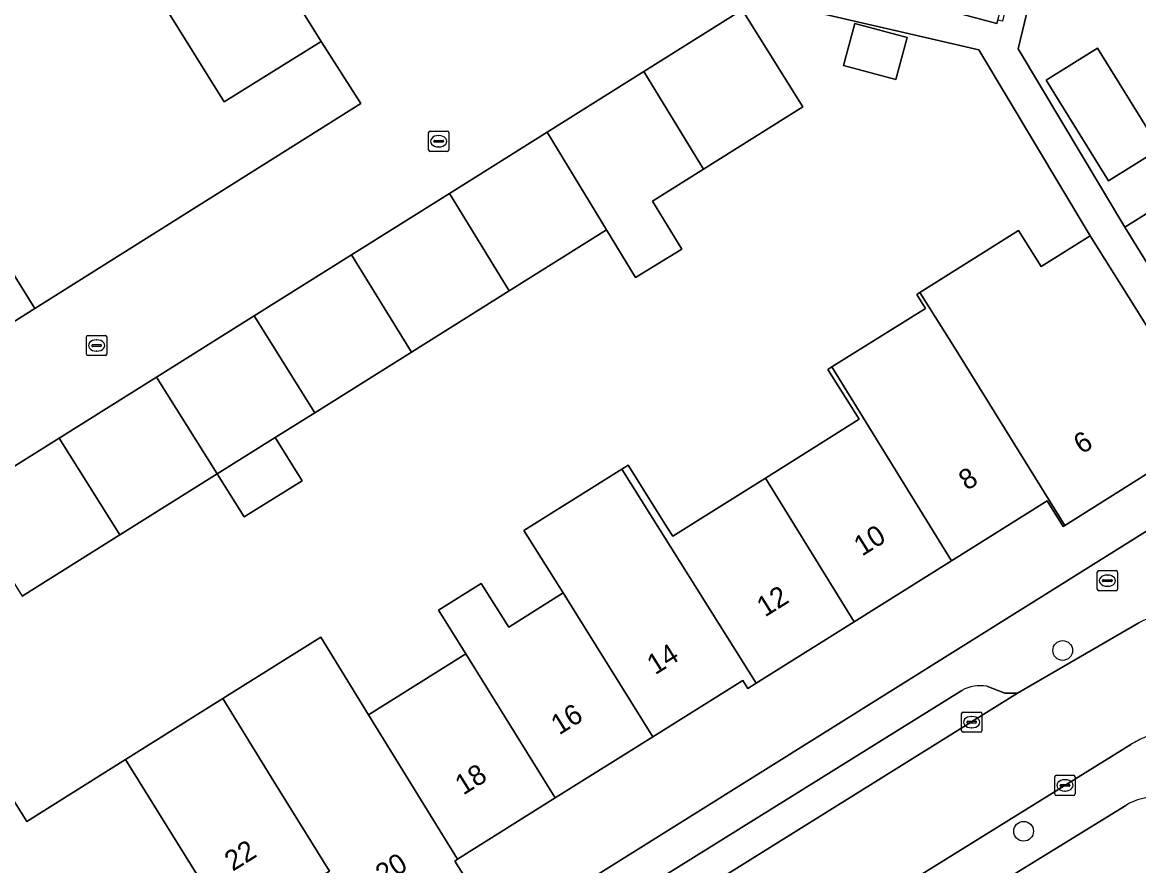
# Model space of a CAD drawing. Extents: x 157767 to 159172, y 387839 to 389425.
# Drawn here: x 158585.1 to 158640.4, y 388070.6 to 388112.4 of the extents above; entities that cross this region are included whole.
import ezdxf

# ---------------------------------------------------------------- set-up
doc = ezdxf.new("R2010")
doc.units = 0
for name, color, linetype in [('IMGEO_Boom', 7, 'Continuous'), ('IMGEO_Brandkraan', 7, 'Continuous'), ('IMGEO_Erf', 7, 'Continuous'), ('IMGEO_Kolk', 7, 'Continuous'), ('IMGEO_Muur', 7, 'Continuous'), ('IMGEO_Pand', 7, 'Continuous'), ('IMGEO_Pand_nummerreeks', 7, 'Continuous'), ('IMGEO_Parkeervlak_open', 7, 'Continuous'), ('IMGEO_Rijbaan_lokaal_open', 7, 'Continuous'), ('IMGEO_Rioolput', 7, 'Continuous'), ('IMGEO_Voetpad_open', 7, 'Continuous')]:
    doc.layers.add(name, color=color, linetype=linetype)

msp = doc.modelspace()

# ---------------------------------------------------------------- linework, layer by layer
at = {"layer": 'IMGEO_Boom'}
for centre in [(158636.608, 388081.306), (158634.673, 388072.349)]:
    msp.add_circle(centre, 0.489, dxfattribs=at)
at = {"layer": 'IMGEO_Brandkraan'}
for p, q in [((158638.322, 388084.338), (158638.322, 388085.19)), ((158638.397, 388085.264), (158639.249, 388085.264)), ((158639.323, 388085.19), (158639.323, 388084.338)), ((158638.581, 388084.758), (158638.581, 388084.77)), ((158639.019, 388084.721), (158638.621, 388084.721)), ((158638.624, 388084.807), (158639.022, 388084.807)), ((158638.81, 388085.044), (158638.835, 388085.044)), ((158639.065, 388084.77), (158639.065, 388084.758)), ((158639.249, 388084.264), (158638.397, 388084.264)), ((158638.833, 388084.484), (158638.808, 388084.484))]:
    msp.add_line(p, q, dxfattribs=at)
for points in [[(158638.322, 388084.338), (158638.322, 388085.19)], [(158638.397, 388085.264), (158639.249, 388085.264)], [(158639.323, 388085.19), (158639.323, 388084.338)], [(158639.249, 388084.264), (158638.397, 388084.264)]]:
    msp.add_lwpolyline(points, dxfattribs=at)
for centre, radius, start, end in [((158638.399, 388085.188), 0.0765, 91.552, 178.448), ((158638.399, 388085.188), 0.0765, 91.552, 178.448), ((158639.247, 388085.188), 0.0765, 1.552, 88.448), ((158639.247, 388085.188), 0.0765, 1.552, 88.448), ((158638.621, 388084.767), 0.0403, 85.8775, 175.7526), ((158638.618, 388084.757), 0.0366, 178.938, 274.7102), ((158639.022, 388084.764), 0.043, 264.8664, 352.4533), ((158639.026, 388084.769), 0.0386, 1.7309, 96.639), ((158638.399, 388084.34), 0.0765, 181.552, 268.448), ((158638.399, 388084.34), 0.0765, 181.552, 268.448), ((158639.247, 388084.34), 0.0765, 271.552, 358.448), ((158639.247, 388084.34), 0.0765, 271.552, 358.448)]:
    msp.add_arc(centre, radius, start, end, dxfattribs=at)
for centre, major_axis, ratio, start_param, end_param in [((158638.809, 388084.764), (-0.387, 0.002), 0.722429, 4.712389, 7.853982), ((158638.834, 388084.764), (-0.39, 0.002), 0.717154, 1.570796, 4.712389)]:
    msp.add_ellipse(centre, major_axis=major_axis, ratio=ratio, start_param=start_param, end_param=end_param, dxfattribs=at)
at = {"layer": 'IMGEO_Erf'}
for points in [[(158641.347, 388140.021), (158634.406, 388111.104), (158639.682, 388102.281), (158642.648, 388104.119)], [(158584.422, 388100.295), (158585.707, 388098.251), (158601.853, 388108.405), (158599.89, 388111.478), (158595.079, 388108.477), (158591.985, 388113.437), (158588.967, 388118.275), (158585.949, 388123.113), (158582.913, 388127.981)], [(158584.145, 388074.678), (158585.3, 388072.835), (158590.193, 388075.903), (158595.012, 388078.925), (158595.324, 388079.121), (158599.864, 388081.968), (158602.235, 388078.12), (158607.042, 388081.134), (158605.687, 388083.295), (158607.814, 388084.628), (158609.169, 388082.468), (158611.861, 388084.156), (158609.923, 388087.246), (158614.781, 388090.293), (158615.088, 388090.485), (158617.026, 388087.395), (158617.293, 388086.969), (158621.882, 388089.847), (158626.522, 388092.757), (158624.978, 388095.223), (158625.181, 388095.35), (158629.818, 388098.252), (158629.383, 388098.947), (158629.526, 388099.037), (158634.425, 388102.107), (158635.54, 388100.328), (158637.971, 388101.852), (158632.456, 388111.061), (158621.79, 388113.525)], [(158620.734, 388113.04), (158623.742, 388108.243), (158618.814, 388105.153), (158616.287, 388103.569), (158617.739, 388101.181), (158615.446, 388099.787), (158614.014, 388102.143), (158609.2, 388099.125), (158604.362, 388096.091), (158599.566, 388093.084), (158597.602, 388091.852), (158598.941, 388089.717), (158596.076, 388087.92), (158594.737, 388090.056), (158589.913, 388087.032), (158585.067, 388083.993)], [(158645.347, 388090.085), (158643.277, 388093.387), (158640.822, 388091.848), (158641.619, 388090.577), (158636.72, 388087.505), (158636.629, 388087.448), (158635.832, 388088.719), (158631.1, 388085.752), (158626.274, 388082.726), (158621.428, 388079.688), (158621.012, 388079.427), (158620.764, 388079.821), (158616.316, 388077.032), (158611.48, 388074), (158606.643, 388070.967), (158606.501, 388070.878), (158607.378, 388069.481)], [(158594.021, 388057.981), (158645.347, 388090.085)], [(158639.729, 388073.631), (158629.395, 388067.278)]]:
    msp.add_lwpolyline(points, dxfattribs=at)
for points in [[(158625.756, 388110.278), (158626.316, 388112.365), (158628.901, 388111.671), (158628.341, 388109.585)], [(158638.871, 388104.576), (158635.784, 388109.56), (158638.336, 388111.141), (158641.423, 388106.158)]]:
    msp.add_lwpolyline(points, close=True, dxfattribs=at)
msp.add_arc((158641.236, 388071.168), 2.888, 53.8682, 121.458, dxfattribs=at)
at = {"layer": 'IMGEO_Kolk'}
for p, q in [((158588.26, 388095.986), (158588.26, 388096.838)), ((158588.335, 388096.912), (158589.187, 388096.912)), ((158589.261, 388096.838), (158589.261, 388095.986)), ((158588.519, 388096.406), (158588.519, 388096.418)), ((158588.957, 388096.369), (158588.559, 388096.369)), ((158588.562, 388096.455), (158588.96, 388096.455)), ((158588.748, 388096.692), (158588.773, 388096.692)), ((158589.003, 388096.418), (158589.003, 388096.406)), ((158589.187, 388095.912), (158588.335, 388095.912)), ((158588.771, 388096.132), (158588.746, 388096.132)), ((158631.601, 388077.329), (158631.601, 388078.181)), ((158631.676, 388078.255), (158632.528, 388078.255)), ((158632.089, 388078.035), (158632.114, 388078.035)), ((158632.602, 388078.181), (158632.602, 388077.329)), ((158631.86, 388077.749), (158631.86, 388077.761)), ((158632.298, 388077.712), (158631.9, 388077.712)), ((158631.903, 388077.798), (158632.301, 388077.798)), ((158632.112, 388077.475), (158632.087, 388077.475)), ((158632.344, 388077.761), (158632.344, 388077.749)), ((158632.528, 388077.255), (158631.676, 388077.255)), ((158636.22, 388074.198), (158636.22, 388075.05)), ((158636.295, 388075.124), (158637.147, 388075.124)), ((158636.479, 388074.618), (158636.479, 388074.63)), ((158636.522, 388074.667), (158636.92, 388074.667)), ((158636.708, 388074.904), (158636.733, 388074.904)), ((158636.963, 388074.63), (158636.963, 388074.618)), ((158637.221, 388075.05), (158637.221, 388074.198)), ((158637.147, 388074.124), (158636.295, 388074.124)), ((158636.917, 388074.581), (158636.519, 388074.581)), ((158636.731, 388074.344), (158636.706, 388074.344))]:
    msp.add_line(p, q, dxfattribs=at)
for points in [[(158588.26, 388095.986), (158588.26, 388096.838)], [(158588.335, 388096.912), (158589.187, 388096.912)], [(158589.261, 388096.838), (158589.261, 388095.986)], [(158589.187, 388095.912), (158588.335, 388095.912)], [(158631.601, 388077.329), (158631.601, 388078.181)], [(158631.676, 388078.255), (158632.528, 388078.255)], [(158632.602, 388078.181), (158632.602, 388077.329)], [(158632.528, 388077.255), (158631.676, 388077.255)], [(158636.22, 388074.198), (158636.22, 388075.05)], [(158636.295, 388075.124), (158637.147, 388075.124)], [(158637.221, 388075.05), (158637.221, 388074.198)], [(158637.147, 388074.124), (158636.295, 388074.124)]]:
    msp.add_lwpolyline(points, dxfattribs=at)
for centre, radius, start, end in [((158588.337, 388096.836), 0.0765, 91.552, 178.448), ((158588.337, 388096.836), 0.0765, 91.552, 178.448), ((158589.185, 388096.836), 0.0765, 1.552, 88.448), ((158589.185, 388096.836), 0.0765, 1.552, 88.448), ((158588.559, 388096.415), 0.0403, 85.8775, 175.7526), ((158588.556, 388096.405), 0.0366, 178.938, 274.7102), ((158588.96, 388096.412), 0.043, 264.8664, 352.4533), ((158588.964, 388096.417), 0.0386, 1.7309, 96.639), ((158588.337, 388095.988), 0.0765, 181.552, 268.448), ((158588.337, 388095.988), 0.0765, 181.552, 268.448), ((158589.185, 388095.988), 0.0765, 271.552, 358.448), ((158589.185, 388095.988), 0.0765, 271.552, 358.448), ((158631.678, 388078.179), 0.0765, 91.552, 178.448), ((158631.678, 388078.179), 0.0765, 91.552, 178.448), ((158632.526, 388078.179), 0.0765, 1.552, 88.448), ((158632.526, 388078.179), 0.0765, 1.552, 88.448), ((158631.9, 388077.758), 0.0403, 85.8775, 175.7526), ((158631.897, 388077.748), 0.0366, 178.938, 274.7102), ((158632.301, 388077.755), 0.043, 264.8664, 352.4533), ((158632.305, 388077.76), 0.0386, 1.7309, 96.639), ((158631.678, 388077.331), 0.0765, 181.552, 268.448), ((158631.678, 388077.331), 0.0765, 181.552, 268.448), ((158632.526, 388077.331), 0.0765, 271.552, 358.448), ((158632.526, 388077.331), 0.0765, 271.552, 358.448), ((158636.297, 388075.048), 0.0765, 91.552, 178.448), ((158636.297, 388075.048), 0.0765, 91.552, 178.448), ((158636.519, 388074.627), 0.0403, 85.8775, 175.7526), ((158636.924, 388074.629), 0.0386, 1.7309, 96.639), ((158637.145, 388075.048), 0.0765, 1.552, 88.448), ((158637.145, 388075.048), 0.0765, 1.552, 88.448), ((158636.297, 388074.2), 0.0765, 181.552, 268.448), ((158636.297, 388074.2), 0.0765, 181.552, 268.448), ((158636.516, 388074.617), 0.0366, 178.938, 274.7102), ((158636.92, 388074.624), 0.043, 264.8664, 352.4533), ((158637.145, 388074.2), 0.0765, 271.552, 358.448), ((158637.145, 388074.2), 0.0765, 271.552, 358.448)]:
    msp.add_arc(centre, radius, start, end, dxfattribs=at)
for centre, major_axis, ratio, start_param, end_param in [((158588.747, 388096.412), (-0.387, 0.002), 0.722429, 4.712389, 7.853982), ((158588.772, 388096.412), (-0.39, 0.002), 0.717154, 1.570796, 4.712389), ((158632.088, 388077.755), (-0.387, 0.002), 0.722429, 4.712389, 7.853982), ((158632.113, 388077.755), (-0.39, 0.002), 0.717154, 1.570796, 4.712389), ((158636.707, 388074.624), (-0.387, 0.002), 0.722429, 4.712389, 7.853982), ((158636.732, 388074.624), (-0.39, 0.002), 0.717154, 1.570796, 4.712389)]:
    msp.add_ellipse(centre, major_axis=major_axis, ratio=ratio, start_param=start_param, end_param=end_param, dxfattribs=at)
at = {"layer": 'IMGEO_Muur'}
msp.add_lwpolyline([(158585.707, 388098.251), (158601.853, 388108.405), (158599.89, 388111.478)], dxfattribs=at)
at = {"layer": 'IMGEO_Pand'}
for points in [[(158591.985, 388113.437), (158595.079, 388108.477), (158599.89, 388111.478), (158596.784, 388116.456)], [(158629.286, 388113.556), (158629.257, 388113.448), (158633.344, 388112.365), (158633.389, 388112.536), (158633.844, 388114.252), (158629.757, 388115.335)], [(158615.862, 388109.985), (158618.814, 388105.153), (158623.742, 388108.243), (158620.734, 388113.04)], [(158625.756, 388110.278), (158628.341, 388109.585), (158628.901, 388111.671), (158626.316, 388112.365)], [(158635.784, 388109.56), (158638.871, 388104.576), (158641.423, 388106.158), (158638.336, 388111.141)], [(158615.862, 388109.985), (158611.073, 388106.982), (158614.014, 388102.143), (158615.446, 388099.787), (158617.739, 388101.181), (158616.287, 388103.569), (158618.814, 388105.153)], [(158606.236, 388103.948), (158609.2, 388099.125), (158614.014, 388102.143), (158611.073, 388106.982)], [(158645.761, 388106.048), (158644.364, 388105.183), (158642.648, 388104.119), (158639.682, 388102.281), (158643.095, 388096.772), (158646.062, 388098.61), (158649.208, 388100.559)], [(158584.422, 388100.295), (158583.099, 388101.1), (158581.484, 388100.084), (158578.413, 388104.968), (158569.685, 388099.464), (158572.625, 388094.751), (158573.894, 388095.549), (158574.08, 388095.253), (158574.802, 388095.703), (158576.734, 388092.607), (158585.707, 388098.251)], [(158601.393, 388100.912), (158604.362, 388096.091), (158609.2, 388099.125), (158606.236, 388103.948)], [(158629.526, 388099.037), (158631.25, 388096.32), (158636.72, 388087.505), (158641.619, 388090.577), (158640.822, 388091.848), (158643.277, 388093.387), (158639.872, 388098.818), (158637.971, 388101.852), (158635.54, 388100.328), (158634.425, 388102.107)], [(158599.566, 388093.084), (158604.362, 388096.091), (158601.393, 388100.912), (158596.563, 388097.883)], [(158631.1, 388085.752), (158635.832, 388088.719), (158636.629, 388087.448), (158636.72, 388087.505), (158631.25, 388096.32), (158629.526, 388099.037), (158629.383, 388098.947), (158629.818, 388098.252), (158625.181, 388095.35)], [(158596.563, 388097.883), (158591.725, 388094.849), (158594.737, 388090.056), (158597.602, 388091.852), (158599.566, 388093.084)], [(158631.1, 388085.752), (158625.181, 388095.35), (158624.978, 388095.223), (158626.522, 388092.757), (158621.882, 388089.847), (158626.274, 388082.726)], [(158586.899, 388091.823), (158589.913, 388087.032), (158594.737, 388090.056), (158591.725, 388094.849)], [(158586.899, 388091.823), (158582.069, 388088.794), (158585.067, 388083.993), (158589.913, 388087.032)], [(158597.602, 388091.852), (158594.737, 388090.056), (158596.076, 388087.92), (158598.941, 388089.717)], [(158611.861, 388084.156), (158616.316, 388077.032), (158620.764, 388079.821), (158621.012, 388079.427), (158621.428, 388079.688), (158614.781, 388090.293), (158609.923, 388087.246)], [(158626.274, 388082.726), (158621.882, 388089.847), (158617.293, 388086.969), (158617.026, 388087.395), (158615.088, 388090.485), (158614.781, 388090.293), (158621.428, 388079.688)], [(158611.861, 388084.156), (158609.169, 388082.468), (158607.814, 388084.628), (158605.687, 388083.295), (158607.042, 388081.134), (158611.48, 388074), (158616.316, 388077.032)], [(158602.235, 388078.12), (158599.864, 388081.968), (158595.324, 388079.121), (158595.012, 388078.925), (158597.544, 388074.82), (158600.291, 388070.368), (158599.852, 388070.093), (158602.252, 388066.267), (158602.662, 388066.524), (158607.378, 388069.481), (158606.501, 388070.878), (158606.643, 388070.967)], [(158602.235, 388078.12), (158606.643, 388070.967), (158611.48, 388074), (158607.042, 388081.134)], [(158595.012, 388078.925), (158590.193, 388075.903), (158594.557, 388068.896), (158594.284, 388068.725), (158595.241, 388067.201), (158595.508, 388067.368), (158599.852, 388070.093), (158600.291, 388070.368), (158597.544, 388074.82)], [(158590.193, 388075.903), (158585.3, 388072.835), (158584.145, 388074.678), (158581.379, 388072.944), (158581.281, 388072.883), (158584.968, 388067.145), (158587.528, 388068.75), (158589.446, 388065.691), (158594.284, 388068.725), (158594.557, 388068.896)]]:
    msp.add_lwpolyline(points, close=True, dxfattribs=at)
at = {"layer": 'IMGEO_Parkeervlak_open'}
for points in [[(158598.186, 388056.371), (158604.468, 388060.381), (158606.82, 388061.883), (158615.518, 388067.436), (158634.377, 388079.187)], [(158631.617, 388079.33), (158599.57, 388059.375)], [(158634.377, 388079.187), (158633.748, 388079.19), (158632.851, 388079.531)]]:
    msp.add_lwpolyline(points, dxfattribs=at)
msp.add_arc((158632.525, 388077.644), 1.915, 80.2022, 118.3005, dxfattribs=at)
at = {"layer": 'IMGEO_Rijbaan_lokaal_open'}
for points in [[(158582.069, 388088.794), (158586.899, 388091.823), (158591.725, 388094.849), (158596.563, 388097.883), (158601.393, 388100.912), (158606.236, 388103.948), (158611.073, 388106.982), (158615.862, 388109.985), (158620.734, 388113.04), (158618.743, 388116.175), (158610.958, 388118.109), (158609.89, 388117.469), (158605.058, 388114.455), (158601.996, 388119.363), (158600.477, 388121.799), (158597.466, 388126.625), (158594.453, 388131.456), (158591.435, 388136.293), (158588.425, 388141.119), (158585.412, 388145.95), (158582.398, 388150.78)], [(158584.695, 388135.836), (158587.729, 388130.972), (158590.759, 388126.115), (158593.769, 388121.29), (158596.784, 388116.456), (158599.89, 388111.478), (158601.853, 388108.405), (158585.707, 388098.251), (158576.734, 388092.607)], [(158640.372, 388082.674), (158634.377, 388079.187), (158615.518, 388067.436), (158606.82, 388061.883), (158609.497, 388057.581), (158610.247, 388058.053), (158619.775, 388064.037), (158629.892, 388070.391), (158639.978, 388076.645)]]:
    msp.add_lwpolyline(points, dxfattribs=at)
for centre, radius, start, end in [((158643.729, 388075.717), 7.725, 83.6439, 115.7569), ((158642.76, 388072.165), 5.273, 112.7604, 121.8427)]:
    msp.add_arc(centre, radius, start, end, dxfattribs=at)
at = {"layer": 'IMGEO_Rioolput'}
for p, q in [((158605.204, 388106.105), (158605.204, 388106.957)), ((158605.279, 388107.031), (158606.131, 388107.031)), ((158605.692, 388106.811), (158605.717, 388106.811)), ((158606.205, 388106.957), (158606.205, 388106.105)), ((158605.463, 388106.525), (158605.463, 388106.537)), ((158605.901, 388106.488), (158605.503, 388106.488)), ((158605.506, 388106.574), (158605.904, 388106.574)), ((158605.715, 388106.251), (158605.69, 388106.251)), ((158605.947, 388106.537), (158605.947, 388106.525)), ((158606.131, 388106.031), (158605.279, 388106.031))]:
    msp.add_line(p, q, dxfattribs=at)
for points in [[(158605.204, 388106.105), (158605.204, 388106.957)], [(158605.279, 388107.031), (158606.131, 388107.031)], [(158606.205, 388106.957), (158606.205, 388106.105)], [(158606.131, 388106.031), (158605.279, 388106.031)]]:
    msp.add_lwpolyline(points, dxfattribs=at)
for centre, radius, start, end in [((158605.281, 388106.955), 0.0765, 91.552, 178.448), ((158605.281, 388106.955), 0.0765, 91.552, 178.448), ((158606.129, 388106.955), 0.0765, 1.552, 88.448), ((158606.129, 388106.955), 0.0765, 1.552, 88.448), ((158605.503, 388106.534), 0.0403, 85.8775, 175.7526), ((158605.5, 388106.524), 0.0366, 178.938, 274.7102), ((158605.904, 388106.531), 0.043, 264.8664, 352.4533), ((158605.908, 388106.536), 0.0386, 1.7309, 96.639), ((158605.281, 388106.107), 0.0765, 181.552, 268.448), ((158605.281, 388106.107), 0.0765, 181.552, 268.448), ((158606.129, 388106.107), 0.0765, 271.552, 358.448), ((158606.129, 388106.107), 0.0765, 271.552, 358.448)]:
    msp.add_arc(centre, radius, start, end, dxfattribs=at)
for centre, major_axis, ratio, start_param, end_param in [((158605.691, 388106.531), (-0.387, 0.002), 0.722429, 4.712389, 7.853982), ((158605.716, 388106.531), (-0.39, 0.002), 0.717154, 1.570796, 4.712389)]:
    msp.add_ellipse(centre, major_axis=major_axis, ratio=ratio, start_param=start_param, end_param=end_param, dxfattribs=at)
at = {"layer": 'IMGEO_Voetpad_open'}
msp.add_lwpolyline([(158639.682, 388102.281), (158634.406, 388111.104), (158641.347, 388140.021), (158640.111, 388140.318), (158638.777, 388134.761), (158637.649, 388129.891), (158636.799, 388126.225), (158633.624, 388112.478), (158633.389, 388112.536), (158633.344, 388112.365), (158629.257, 388113.448), (158629.286, 388113.556), (158618.743, 388116.175), (158620.734, 388113.04), (158621.79, 388113.525), (158632.456, 388111.061), (158637.971, 388101.852), (158639.872, 388098.818), (158643.277, 388093.387), (158645.347, 388090.085), (158646.674, 388090.915), (158646.227, 388091.63), (158643.095, 388096.772)], close=True, dxfattribs=at)
for points in [[(158686.368, 388027.385), (158661.715, 388067.158), (158659.117, 388071.321), (158646.863, 388091.033), (158646.674, 388090.915), (158645.347, 388090.085), (158594.021, 388057.981)], [(158632.851, 388079.531), (158633.748, 388079.19), (158634.377, 388079.187), (158640.372, 388082.674)], [(158599.57, 388059.375), (158631.617, 388079.33)], [(158639.978, 388076.645), (158629.892, 388070.391), (158619.775, 388064.037), (158620.046, 388063.617), (158614.61, 388060.203), (158615.585, 388058.556), (158620.959, 388061.95), (158629.395, 388067.278)], [(158629.395, 388067.278), (158639.729, 388073.631)]]:
    msp.add_lwpolyline(points, dxfattribs=at)
for centre, radius, start, end in [((158643.729, 388075.717), 7.725, 83.6439, 115.7569), ((158632.525, 388077.644), 1.915, 80.2022, 118.3005), ((158642.76, 388072.165), 5.273, 112.7604, 121.8427), ((158641.236, 388071.168), 2.888, 53.8682, 121.458)]:
    msp.add_arc(centre, radius, start, end, dxfattribs=at)

# ---------------------------------------------------------------- texts
at = {"layer": 'IMGEO_Pand_nummerreeks'}
for s, rotation, p in [('6', 32.0899, (158637.551, 388091.001)), ('8', 32.0868, (158631.863, 388089.205)), ('10', 32.0868, (158626.671, 388085.951)), ('12', 32.0868, (158621.864, 388082.936)), ('14', 32.088, (158616.425, 388080.074)), ('16', 32.088, (158611.671, 388077.093)), ('18', 32.088, (158606.919, 388074.114)), ('22', 32.0971, (158595.505, 388070.342)), ('20', 32.0856, (158602.983, 388069.7))]:
    msp.add_text(s, height=1, rotation=rotation, dxfattribs=at).set_placement(p)

doc.saveas('drawing.dxf')
